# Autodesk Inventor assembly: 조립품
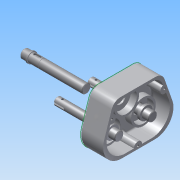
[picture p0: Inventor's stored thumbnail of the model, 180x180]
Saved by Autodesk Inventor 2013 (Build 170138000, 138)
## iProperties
Created: 2014-12
Part Number: 조립품
Document SubType Name: Assembly
Designer: Administrator
Author: Administrator
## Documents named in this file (5)
- C:\Users\Administrator\Desktop\441209V1007\조립품.iam
- C:\Users\Administrator\Desktop\441209V1007\본체.ipt
- C:\Users\Administrator\Desktop\441209V1007\오일시일-D-15.ipt
- C:\Users\Administrator\Desktop\441209V1007\서브축.ipt
- C:\Users\Administrator\Desktop\441209V1007\메인축.ipt
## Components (2 placed, 1 different names)
1. KS B 2804 D D - 15 30 7:1
2. KS B 2804 D D - 15 30 7:2
